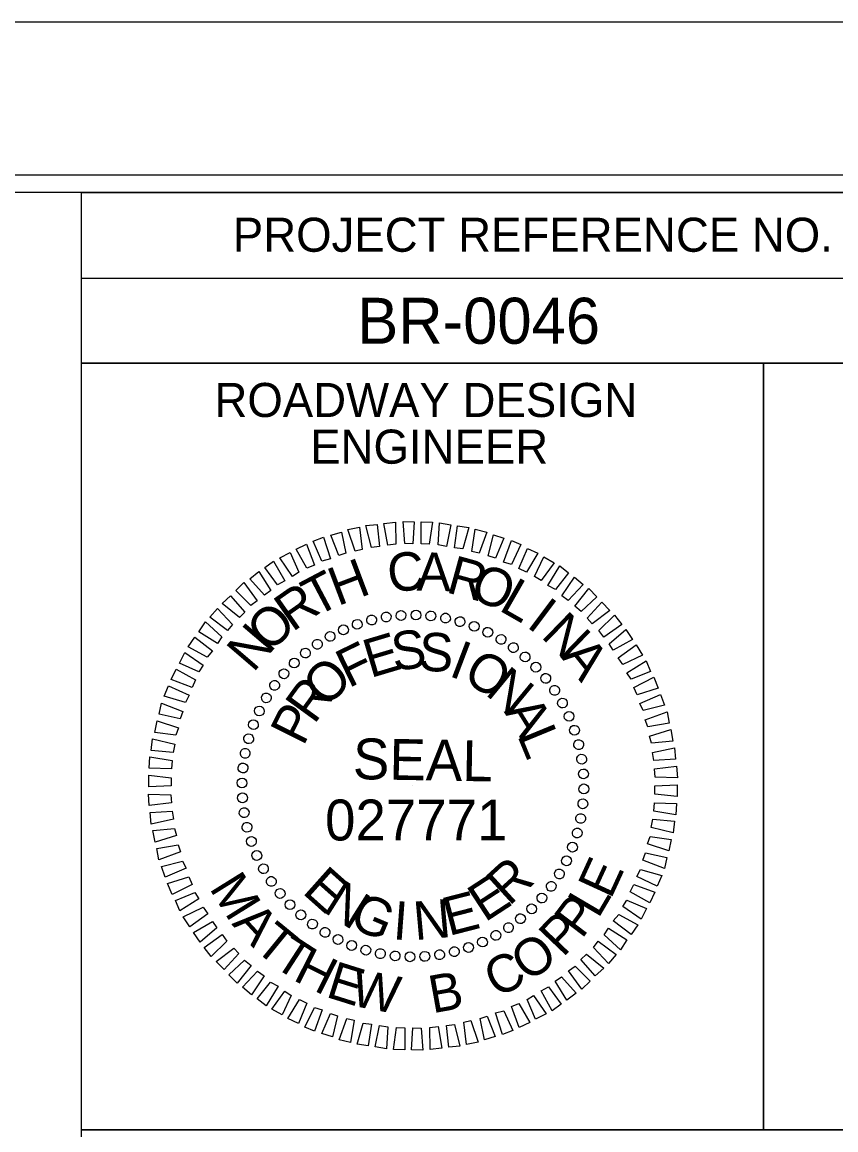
# Model space of a CAD drawing. Extents: x 1497225 to 1499181, y 579958 to 582278.
# Drawn here: x 1498683.5 to 1498802.9, y 580895.5 to 581058 of the extents above; entities that cross this region are included whole.
import ezdxf

# ---------------------------------------------------------------- set-up
doc = ezdxf.new("R2010")
doc.units = 0
for name, color, linetype in [('Sheet Cutting Line CELL', 7, 'Continuous'), ('Sheet Data Field CELL', 7, 'Continuous'), ('Sheet Plot Border Inside CELL', 7, 'Continuous'), ('Sheet Plot Border Outside CELL', 7, 'Continuous'), ('Sheet Professional Seal CELL', 7, 'Continuous'), ('Sheet Sticker Exception Certification CELL', 7, 'Continuous'), ('Sheet Typical CELL', 7, 'Continuous')]:
    doc.layers.add(name, color=color, linetype=linetype)

msp = doc.modelspace()

# ---------------------------------------------------------------- linework, layer by layer
at = {"layer": 'Sheet Cutting Line CELL'}
msp.add_line((1498909.23, 581058.02), (1497225.23, 581058.02), dxfattribs=at)
at = {"layer": 'Sheet Plot Border Inside CELL'}
msp.add_lwpolyline([(1498904.73, 581035.57), (1497238.23, 581035.57), (1497238.23, 579980.47), (1498904.73, 579980.47)], close=True, dxfattribs=at)
at = {"layer": 'Sheet Plot Border Outside CELL'}
msp.add_lwpolyline([(1498909.23, 581058.02), (1497225.23, 581058.02), (1497225.23, 579958.02), (1498909.23, 579958.02)], close=True, dxfattribs=at)
at = {"layer": 'Sheet Professional Seal CELL'}
for p, q in [((1498732.61, 580969.69), (1498732.61, 580969.69)), ((1498734.71, 580970.29), (1498734.71, 580970.29)), ((1498736.91, 580970.69), (1498736.91, 580970.69)), ((1498739.06, 580970.99), (1498739.06, 580970.99)), ((1498741.26, 580971.04), (1498741.26, 580971.04)), ((1498743.46, 580970.89), (1498743.46, 580970.89)), ((1498745.61, 580970.54), (1498745.61, 580970.54)), ((1498747.71, 580970.09), (1498747.71, 580970.09)), ((1498730.61, 580968.89), (1498730.61, 580968.89)), ((1498749.81, 580969.39), (1498749.81, 580969.39)), ((1498751.81, 580968.49), (1498751.81, 580968.49)), ((1498726.76, 580966.74), (1498726.76, 580966.74)), ((1498728.66, 580967.89), (1498728.66, 580967.89)), ((1498753.76, 580967.49), (1498753.76, 580967.49)), ((1498725.01, 580965.49), (1498725.01, 580965.49)), ((1498755.56, 580966.24), (1498755.56, 580966.24)), ((1498757.31, 580964.89), (1498757.31, 580964.89)), ((1498723.36, 580963.99), (1498723.36, 580963.99)), ((1498758.86, 580963.39), (1498758.86, 580963.39)), ((1498721.86, 580962.44), (1498721.86, 580962.44)), ((1498760.36, 580961.74), (1498760.36, 580961.74)), ((1498720.51, 580960.69), (1498720.51, 580960.69)), ((1498761.61, 580959.99), (1498761.61, 580959.99)), ((1498719.26, 580958.89), (1498719.26, 580958.89)), ((1498718.26, 580956.94), (1498718.26, 580956.94)), ((1498762.76, 580958.09), (1498762.76, 580958.09)), ((1498717.36, 580954.94), (1498717.36, 580954.94)), ((1498763.76, 580956.14), (1498763.76, 580956.14)), ((1498764.56, 580954.14), (1498764.56, 580954.14)), ((1498716.66, 580952.84), (1498716.66, 580952.84)), ((1498765.16, 580952.04), (1498765.16, 580952.04)), ((1498716.21, 580950.74), (1498716.21, 580950.74)), ((1498715.86, 580948.59), (1498715.86, 580948.59)), ((1498765.56, 580949.84), (1498765.56, 580949.84)), ((1498765.86, 580947.69), (1498765.86, 580947.69)), ((1498715.71, 580946.39), (1498715.71, 580946.39)), ((1498740.81, 580945.94), (1498740.81, 580945.94)), ((1498765.91, 580945.49), (1498765.91, 580945.49)), ((1498715.76, 580944.19), (1498715.76, 580944.19)), ((1498716.06, 580942.04), (1498716.06, 580942.04)), ((1498765.76, 580943.29), (1498765.76, 580943.29)), ((1498765.41, 580941.14), (1498765.41, 580941.14)), ((1498716.46, 580939.84), (1498716.46, 580939.84)), ((1498764.96, 580939.04), (1498764.96, 580939.04)), ((1498717.06, 580937.74), (1498717.06, 580937.74)), ((1498717.86, 580935.74), (1498717.86, 580935.74)), ((1498764.26, 580936.94), (1498764.26, 580936.94)), ((1498718.86, 580933.79), (1498718.86, 580933.79)), ((1498763.36, 580934.94), (1498763.36, 580934.94)), ((1498762.36, 580932.99), (1498762.36, 580932.99)), ((1498720.01, 580931.89), (1498720.01, 580931.89)), ((1498761.11, 580931.19), (1498761.11, 580931.19)), ((1498721.26, 580930.14), (1498721.26, 580930.14)), ((1498759.76, 580929.44), (1498759.76, 580929.44)), ((1498722.76, 580928.49), (1498722.76, 580928.49)), ((1498758.26, 580927.89), (1498758.26, 580927.89)), ((1498724.31, 580926.99), (1498724.31, 580926.99)), ((1498756.61, 580926.39), (1498756.61, 580926.39)), ((1498726.06, 580925.64), (1498726.06, 580925.64)), ((1498727.86, 580924.39), (1498727.86, 580924.39)), ((1498754.86, 580925.14), (1498754.86, 580925.14)), ((1498729.81, 580923.39), (1498729.81, 580923.39)), ((1498731.81, 580922.49), (1498731.81, 580922.49)), ((1498751.01, 580922.99), (1498751.01, 580922.99)), ((1498752.96, 580923.99), (1498752.96, 580923.99)), ((1498733.91, 580921.79), (1498733.91, 580921.79)), ((1498736.01, 580921.34), (1498736.01, 580921.34)), ((1498738.16, 580920.99), (1498738.16, 580920.99)), ((1498740.36, 580920.84), (1498740.36, 580920.84)), ((1498742.56, 580920.89), (1498742.56, 580920.89)), ((1498744.71, 580921.19), (1498744.71, 580921.19)), ((1498746.91, 580921.59), (1498746.91, 580921.59)), ((1498749.01, 580922.19), (1498749.01, 580922.19))]:
    msp.add_line(p, q, dxfattribs=at)
for points in [[(1498734.71, 580980.94), (1498733.91, 580984.14), (1498735.56, 580984.29), (1498735.91, 580981.09)], [(1498737.11, 580981.24), (1498736.56, 580984.44), (1498738.26, 580984.64), (1498738.31, 580981.39)], [(1498739.61, 580981.49), (1498739.36, 580984.74), (1498741.01, 580984.69), (1498740.81, 580981.44)], [(1498742.01, 580981.44), (1498742.01, 580984.69), (1498743.66, 580984.64), (1498743.21, 580981.39)], [(1498744.51, 580981.29), (1498744.71, 580984.54), (1498746.36, 580984.24), (1498745.71, 580981.09)], [(1498729.91, 580979.74), (1498728.76, 580982.74), (1498730.31, 580983.19), (1498730.96, 580980.09)], [(1498732.31, 580980.39), (1498731.26, 580983.54), (1498732.96, 580983.89), (1498733.36, 580980.64)], [(1498746.91, 580980.89), (1498747.36, 580984.09), (1498749.01, 580983.84), (1498748.11, 580980.74)], [(1498749.46, 580980.34), (1498749.96, 580983.59), (1498751.66, 580983.19), (1498750.51, 580980.09)], [(1498751.86, 580979.69), (1498752.61, 580982.79), (1498754.16, 580982.29), (1498752.91, 580979.34)], [(1498725.26, 580977.89), (1498723.66, 580980.69), (1498725.21, 580981.39), (1498726.36, 580978.34)], [(1498727.46, 580978.94), (1498726.16, 580981.84), (1498727.66, 580982.44), (1498728.71, 580979.24)], [(1498754.11, 580978.79), (1498755.26, 580981.94), (1498756.66, 580981.34), (1498755.26, 580978.44)], [(1498723.11, 580976.69), (1498721.26, 580979.39), (1498722.81, 580980.19), (1498724.06, 580977.29)], [(1498756.36, 580977.84), (1498757.61, 580980.79), (1498759.16, 580980.09), (1498757.46, 580977.29)], [(1498758.66, 580976.69), (1498760.01, 580979.54), (1498761.51, 580978.69), (1498759.61, 580976.09)], [(1498720.91, 580975.44), (1498719.06, 580977.99), (1498720.36, 580978.94), (1498722.01, 580976.04)], [(1498760.61, 580975.34), (1498762.36, 580978.24), (1498763.66, 580977.19), (1498761.71, 580974.74)], [(1498719.01, 580973.94), (1498716.86, 580976.34), (1498718.21, 580977.39), (1498719.96, 580974.59)], [(1498762.66, 580973.84), (1498764.51, 580976.59), (1498765.81, 580975.49), (1498763.61, 580973.14)], [(1498717.01, 580972.39), (1498714.81, 580974.59), (1498716.01, 580975.79), (1498717.96, 580973.09)], [(1498764.56, 580972.29), (1498766.61, 580974.89), (1498767.81, 580973.69), (1498765.51, 580971.54)], [(1498715.36, 580970.64), (1498712.81, 580972.69), (1498714.06, 580973.84), (1498716.16, 580971.44)], [(1498766.36, 580970.54), (1498768.51, 580972.89), (1498769.71, 580971.69), (1498767.11, 580969.74)], [(1498713.61, 580968.74), (1498711.01, 580970.69), (1498712.11, 580971.99), (1498714.31, 580969.64)], [(1498712.11, 580966.84), (1498709.41, 580968.54), (1498710.36, 580969.99), (1498712.76, 580967.79)], [(1498768.11, 580968.74), (1498770.41, 580970.99), (1498771.46, 580969.64), (1498768.81, 580967.74)], [(1498769.61, 580966.79), (1498772.06, 580968.89), (1498773.01, 580967.44), (1498770.21, 580965.84)], [(1498710.61, 580964.84), (1498707.81, 580966.34), (1498708.81, 580967.74), (1498711.41, 580965.74)], [(1498770.91, 580964.74), (1498773.56, 580966.64), (1498774.51, 580965.14), (1498771.61, 580963.74)], [(1498709.41, 580962.69), (1498706.56, 580963.94), (1498707.31, 580965.49), (1498710.01, 580963.64)], [(1498708.41, 580960.39), (1498705.31, 580961.54), (1498706.06, 580963.09), (1498708.91, 580961.49)], [(1498772.21, 580962.54), (1498775.01, 580964.29), (1498775.66, 580962.74), (1498772.81, 580961.59)], [(1498773.21, 580960.39), (1498776.16, 580961.89), (1498776.81, 580960.29), (1498773.71, 580959.29)], [(1498707.41, 580958.19), (1498704.31, 580959.09), (1498704.96, 580960.64), (1498707.96, 580959.24)], [(1498774.11, 580958.04), (1498777.16, 580959.34), (1498777.71, 580957.79), (1498774.61, 580956.99)], [(1498706.66, 580955.79), (1498703.56, 580956.44), (1498703.91, 580958.09), (1498707.06, 580956.84)], [(1498774.91, 580955.64), (1498778.11, 580956.79), (1498778.41, 580955.14), (1498775.26, 580954.59)], [(1498706.01, 580953.39), (1498702.91, 580953.79), (1498703.26, 580955.49), (1498706.41, 580954.44)], [(1498775.51, 580953.24), (1498778.66, 580954.19), (1498778.96, 580952.49), (1498775.81, 580952.19)], [(1498705.61, 580950.84), (1498702.41, 580951.14), (1498702.61, 580952.84), (1498705.86, 580952.04)], [(1498705.36, 580948.44), (1498702.11, 580948.54), (1498702.21, 580950.19), (1498705.46, 580949.64)], [(1498775.96, 580950.84), (1498779.21, 580951.54), (1498779.36, 580949.84), (1498776.16, 580949.64)], [(1498776.26, 580948.44), (1498779.51, 580948.84), (1498779.61, 580947.14), (1498776.36, 580947.24)], [(1498705.31, 580945.94), (1498702.06, 580945.79), (1498702.06, 580947.49), (1498705.31, 580947.14)], [(1498776.31, 580945.94), (1498779.56, 580946.09), (1498779.56, 580944.39), (1498776.31, 580944.74)], [(1498705.36, 580943.44), (1498702.11, 580943.04), (1498702.01, 580944.74), (1498705.26, 580944.64)], [(1498705.66, 580941.04), (1498702.41, 580940.34), (1498702.26, 580942.04), (1498705.46, 580942.24)], [(1498776.26, 580943.44), (1498779.51, 580943.34), (1498779.41, 580941.69), (1498776.16, 580942.24)], [(1498776.01, 580941.04), (1498779.21, 580940.74), (1498779.01, 580939.04), (1498775.76, 580939.84)], [(1498706.11, 580938.64), (1498702.96, 580937.69), (1498702.66, 580939.39), (1498705.81, 580939.69)], [(1498706.71, 580936.24), (1498703.51, 580935.09), (1498703.21, 580936.74), (1498706.36, 580937.29)], [(1498775.61, 580938.49), (1498778.71, 580938.09), (1498778.36, 580936.39), (1498775.21, 580937.44)], [(1498774.96, 580936.09), (1498778.06, 580935.44), (1498777.71, 580933.79), (1498774.56, 580935.04)], [(1498707.51, 580933.84), (1498704.46, 580932.54), (1498703.91, 580934.09), (1498707.01, 580934.89)], [(1498708.41, 580931.49), (1498705.46, 580929.99), (1498704.81, 580931.59), (1498707.91, 580932.59)], [(1498774.21, 580933.69), (1498777.31, 580932.79), (1498776.66, 580931.24), (1498773.66, 580932.64)], [(1498773.21, 580931.49), (1498776.31, 580930.34), (1498775.56, 580928.79), (1498772.71, 580930.39)], [(1498709.41, 580929.34), (1498706.61, 580927.59), (1498705.96, 580929.14), (1498708.81, 580930.29)], [(1498772.21, 580929.19), (1498775.06, 580927.94), (1498774.31, 580926.39), (1498771.61, 580928.24)], [(1498710.71, 580927.14), (1498708.06, 580925.24), (1498707.11, 580926.74), (1498710.01, 580928.14)], [(1498712.01, 580925.09), (1498709.56, 580922.99), (1498708.61, 580924.44), (1498711.41, 580926.04)], [(1498771.01, 580927.04), (1498773.81, 580925.54), (1498772.81, 580924.14), (1498770.21, 580926.14)], [(1498713.51, 580923.14), (1498711.21, 580920.89), (1498710.16, 580922.24), (1498712.81, 580924.14)], [(1498769.51, 580925.04), (1498772.21, 580923.34), (1498771.26, 580921.89), (1498768.86, 580924.09)], [(1498768.01, 580923.14), (1498770.61, 580921.19), (1498769.51, 580919.89), (1498767.31, 580922.24)], [(1498715.26, 580921.34), (1498713.11, 580918.99), (1498711.91, 580920.19), (1498714.51, 580922.14)], [(1498766.26, 580921.24), (1498768.81, 580919.19), (1498767.56, 580918.04), (1498765.46, 580920.44)], [(1498717.06, 580919.59), (1498715.01, 580916.99), (1498713.81, 580918.19), (1498716.11, 580920.34)], [(1498764.61, 580919.49), (1498766.81, 580917.29), (1498765.61, 580916.09), (1498763.66, 580918.79)], [(1498718.96, 580918.04), (1498717.11, 580915.29), (1498715.81, 580916.39), (1498718.01, 580918.74)], [(1498762.61, 580917.94), (1498764.76, 580915.54), (1498763.41, 580914.49), (1498761.66, 580917.29)], [(1498721.01, 580916.54), (1498719.26, 580913.64), (1498717.96, 580914.69), (1498719.91, 580917.14)], [(1498760.71, 580916.44), (1498762.56, 580913.89), (1498761.26, 580912.94), (1498759.61, 580915.84)], [(1498722.96, 580915.19), (1498721.61, 580912.34), (1498720.11, 580913.19), (1498722.01, 580915.79)], [(1498725.26, 580914.04), (1498724.01, 580911.09), (1498722.46, 580911.79), (1498724.16, 580914.59)], [(1498758.51, 580915.19), (1498760.36, 580912.49), (1498758.81, 580911.69), (1498757.56, 580914.59)], [(1498727.51, 580913.09), (1498726.36, 580909.94), (1498724.96, 580910.54), (1498726.36, 580913.44)], [(1498754.16, 580912.94), (1498755.46, 580910.04), (1498753.96, 580909.44), (1498752.91, 580912.64)], [(1498756.36, 580913.99), (1498757.96, 580911.19), (1498756.41, 580910.49), (1498755.26, 580913.54)], [(1498729.76, 580912.19), (1498729.01, 580909.09), (1498727.46, 580909.59), (1498728.71, 580912.54)], [(1498732.16, 580911.54), (1498731.66, 580908.29), (1498729.96, 580908.69), (1498731.11, 580911.79)], [(1498734.71, 580910.99), (1498734.26, 580907.79), (1498732.61, 580908.04), (1498733.51, 580911.14)], [(1498749.31, 580911.49), (1498750.36, 580908.34), (1498748.66, 580907.99), (1498748.26, 580911.24)], [(1498751.71, 580912.14), (1498752.86, 580909.14), (1498751.31, 580908.69), (1498750.66, 580911.79)], [(1498737.11, 580910.59), (1498736.91, 580907.34), (1498735.26, 580907.64), (1498735.91, 580910.79)], [(1498739.61, 580910.44), (1498739.61, 580907.19), (1498737.96, 580907.24), (1498738.41, 580910.49)], [(1498742.01, 580910.39), (1498742.26, 580907.14), (1498740.61, 580907.19), (1498740.81, 580910.44)], [(1498744.51, 580910.64), (1498745.06, 580907.44), (1498743.36, 580907.24), (1498743.31, 580910.49)], [(1498746.91, 580910.94), (1498747.71, 580907.74), (1498746.06, 580907.59), (1498745.71, 580910.79)]]:
    msp.add_lwpolyline(points, close=True, dxfattribs=at)
for centre, major_axis in [((1498736.89, 580970.71), (-0.113, 0.711)), ((1498739.06, 580970.95), (-0.05, 0.718)), ((1498741.25, 580971.01), (0.013, 0.72)), ((1498743.43, 580970.88), (0.075, 0.716)), ((1498745.59, 580970.56), (0.137, 0.707)), ((1498730.61, 580968.85), (-0.293, 0.658)), ((1498732.64, 580969.65), (-0.234, 0.681)), ((1498734.74, 580970.27), (-0.174, 0.699)), ((1498747.72, 580970.04), (0.198, 0.692)), ((1498749.8, 580969.35), (0.258, 0.672)), ((1498728.65, 580967.87), (-0.349, 0.63)), ((1498751.8, 580968.48), (0.316, 0.647)), ((1498753.73, 580967.43), (0.371, 0.617)), ((1498726.78, 580966.73), (-0.403, 0.597)), ((1498755.55, 580966.23), (0.423, 0.582)), ((1498723.39, 580963.98), (-0.5, 0.518)), ((1498725.03, 580965.43), (-0.453, 0.56)), ((1498757.26, 580964.86), (0.472, 0.543)), ((1498721.88, 580962.39), (-0.543, 0.472)), ((1498758.85, 580963.36), (0.518, 0.5)), ((1498720.52, 580960.68), (-0.582, 0.423)), ((1498760.3, 580961.72), (0.56, 0.453)), ((1498761.6, 580959.96), (0.597, 0.403)), ((1498719.31, 580958.85), (-0.617, 0.371)), ((1498762.74, 580958.09), (0.63, 0.349)), ((1498718.27, 580956.93), (-0.647, 0.316)), ((1498763.72, 580956.14), (0.658, 0.293)), ((1498717.4, 580954.92), (-0.672, 0.258)), ((1498764.52, 580954.1), (0.681, 0.234)), ((1498716.7, 580952.85), (-0.692, 0.198)), ((1498765.14, 580952), (0.699, 0.174)), ((1498716.19, 580950.72), (-0.707, 0.137)), ((1498765.58, 580949.86), (0.711, 0.113)), ((1498715.87, 580948.56), (-0.716, 0.075)), ((1498765.83, 580947.69), (0.718, 0.05)), ((1498715.73, 580946.37), (-0.72, 0.013)), ((1498765.89, 580945.5), (0.72, -0.013)), ((1498715.79, 580944.19), (-0.718, -0.05)), ((1498765.75, 580943.31), (0.716, -0.075)), ((1498716.04, 580942.01), (-0.711, -0.113)), ((1498765.43, 580941.15), (0.707, -0.137)), ((1498716.47, 580939.87), (-0.699, -0.174)), ((1498764.92, 580939.02), (0.692, -0.198)), ((1498717.1, 580937.77), (-0.681, -0.234)), ((1498764.22, 580936.95), (0.672, -0.258)), ((1498717.9, 580935.73), (-0.658, -0.293)), ((1498763.35, 580934.94), (0.647, -0.316)), ((1498718.87, 580933.78), (-0.63, -0.349)), ((1498762.31, 580933.02), (0.617, -0.371)), ((1498720.02, 580931.91), (-0.597, -0.403)), ((1498721.32, 580930.15), (-0.56, -0.453)), ((1498761.1, 580931.19), (0.582, -0.423)), ((1498722.77, 580928.51), (-0.518, -0.5)), ((1498759.74, 580929.48), (0.543, -0.472)), ((1498724.36, 580927.01), (-0.472, -0.543)), ((1498758.23, 580927.89), (0.5, -0.518)), ((1498726.07, 580925.65), (-0.423, -0.582)), ((1498754.83, 580925.14), (0.403, -0.597)), ((1498756.59, 580926.45), (0.453, -0.56)), ((1498727.89, 580924.44), (-0.371, -0.617)), ((1498729.81, 580923.39), (-0.316, -0.647)), ((1498752.97, 580924), (0.349, -0.63)), ((1498731.82, 580922.52), (-0.258, -0.672)), ((1498733.9, 580921.83), (-0.198, -0.692)), ((1498746.88, 580921.6), (0.174, -0.699)), ((1498748.97, 580922.22), (0.234, -0.681)), ((1498751.01, 580923.02), (0.293, -0.658)), ((1498736.02, 580921.32), (-0.137, -0.707)), ((1498738.19, 580920.99), (-0.075, -0.716)), ((1498740.37, 580920.86), (-0.013, -0.72)), ((1498742.56, 580920.92), (0.05, -0.718)), ((1498744.73, 580921.16), (0.113, -0.711))]:
    msp.add_ellipse(centre, major_axis=major_axis, ratio=0.999708, dxfattribs=at)
at = {"layer": 'Sheet Sticker Exception Certification CELL'}
for p, q in [((1498692.18, 580871.97), (1498692.18, 580895.47)), ((1498692.18, 580895.47), (1498892.22, 580895.47))]:
    msp.add_line(p, q, dxfattribs=at)
at = {"layer": 'Sheet Typical CELL'}
for p, q in [((1498692.18, 581020.47), (1498892.23, 581020.47)), ((1498792.23, 581007.97), (1498792.23, 580895.52))]:
    msp.add_line(p, q, dxfattribs=at)
for points in [[(1498892.23, 581033.02), (1497392.23, 581033.02), (1497392.23, 579983.02), (1498892.23, 579983.02)], [(1498692.18, 581033.02), (1498892.23, 581033.02), (1498892.23, 581007.97), (1498692.18, 581007.97)], [(1498692.18, 581007.97), (1498792.23, 581007.97), (1498792.23, 580895.47), (1498692.18, 580895.47)], [(1498792.23, 581007.97), (1498892.23, 581007.97), (1498892.23, 580895.47), (1498792.23, 580895.47)]]:
    msp.add_lwpolyline(points, close=True, dxfattribs=at)

# ---------------------------------------------------------------- texts
at = {"layer": 'Sheet Data Field CELL'}
msp.add_text('BR-0046', height=6.75, dxfattribs=at).set_placement((1498732.64, 581010.82))
at = {"layer": 'Sheet Professional Seal CELL'}
for s, height, rotation, p in [('C', 5.64, 6.2199, (1498737.36, 580974.29)), ('A', 5.64, 359.0203, (1498741.31, 580974.59)), ('R', 5.64, 344.6211, (1498745.51, 580974.39)), ('T', 5.64, 27.8198, (1498726.51, 580970.64)), ('H', 5.64, 20.6195, (1498729.76, 580972.29)), ('O', 5.64, 337.4212, (1498748.86, 580973.64)), ('L', 5.64, 330.2209, (1498753.26, 580971.79)), ('R', 5.64, 35.0205, (1498723.11, 580968.44)), ('I', 5.64, 323.0201, (1498757.31, 580969.39)), ('O', 5.64, 42.2217, (1498719.66, 580965.34)), ('N', 5.64, 315.8189, (1498759.46, 580967.84)), ('N', 5.64, 49.4235, (1498717.36, 580962.44)), ('E', 5.64, 16.6111, (1498734.56, 580961.74)), ('S', 5.64, 7.2556, (1498738.01, 580962.79)), ('S', 5.64, 357.9004, (1498741.61, 580962.84)), ('F', 5.64, 25.967, (1498731.36, 580960.24)), ('I', 5.64, 339.1896, (1498745.91, 580962.14)), ('A', 5.64, 308.6172, (1498762.41, 580964.89)), ('O', 5.64, 329.8335, (1498747.91, 580961.44)), ('O', 5.64, 44.6812, (1498728.06, 580957.29)), ('N', 5.64, 320.4766, (1498751.26, 580959.44)), ('R', 5.64, 54.0397, (1498726.31, 580954.84)), ('P', 5.64, 63.3989, (1498724.71, 580951.64)), ('A', 5.64, 301.7603, (1498754.11, 580956.84)), ('L', 5.64, 292.4008, (1498756.06, 580953.39)), ('SEAL', 5.998, 359, (1498731.96, 580946.94)), ('E', 5.5, 65.3458, (1498769.84, 580929.19)), ('E', 5.64, 318.2769, (1498724.41, 580930.29)), ('R', 5.64, 42.4814, (1498754.91, 580928.19)), ('M', 5.5, 301.8863, (1498710.84, 580930.95)), ('E', 5.64, 33.1241, (1498751.36, 580925.84)), ('N', 5.64, 327.634, (1498727.41, 580927.59)), ('G', 5.64, 336.9902, (1498731.21, 580925.34)), ('I', 5.64, 355.7012, (1498737.76, 580923.44)), ('N', 5.64, 5.0564, (1498741.11, 580923.29)), ('E', 5.64, 14.4118, (1498746.06, 580923.89)), ('P', 5.5, 52.9527, (1498765.57, 580923.35)), ('L', 5.5, 59.5356, (1498767.99, 580926.34)), ('A', 5.5, 312.5622, (1498714.13, 580925.66)), ('T', 5.5, 320.748, (1498717.29, 580922.07)), ('P', 5.5, 46.3697, (1498762.81, 580920.66)), ('T', 5.5, 327.0447, (1498720.05, 580919.63)), ('O', 5.5, 35.6652, (1498757.74, 580917.02)), ('H', 5.5, 333.3415, (1498723.06, 580917.51)), ('C', 5.5, 26.7925, (1498753.07, 580914.75)), ('E', 5.5, 342.5863, (1498727.86, 580915.03)), ('W', 5.5, 349.1693, (1498731.49, 580913.75)), ('B', 5.5, 10.2205, (1498743.67, 580912.55))]:
    msp.add_text(s, height=height, rotation=rotation, dxfattribs=at).set_placement(p)
msp.add_text('027771', height=5.998, dxfattribs=at).set_placement((1498727.91, 580937.93))
at = {"layer": 'Sheet Typical CELL'}
for s, height, p in [('PROJECT REFERENCE NO.', 5.0001, (1498714.38, 581024.32)), ('ROADWAY DESIGN', 5.0001, (1498711.68, 581000.07)), ('ENGINEER', 5, (1498725.73, 580993.22))]:
    msp.add_text(s, height=height, dxfattribs=at).set_placement(p)

doc.saveas('drawing.dxf')
